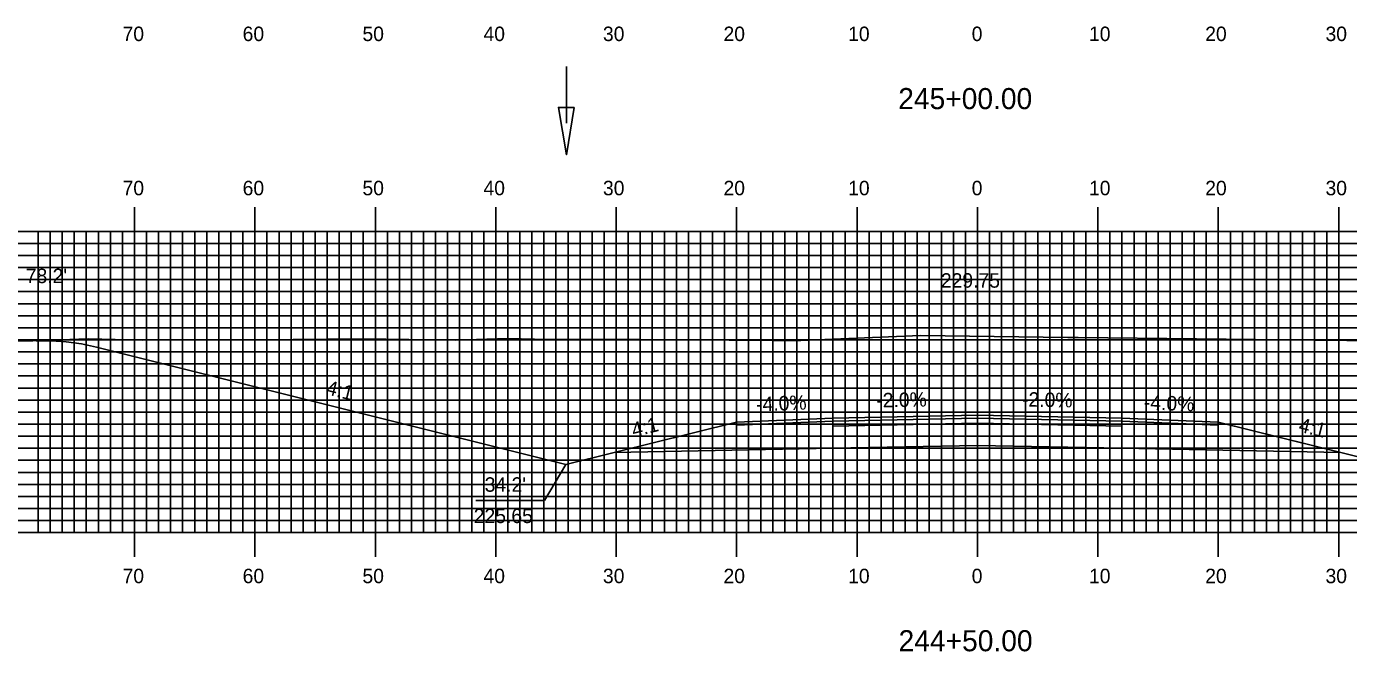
# Model space of a CAD drawing. Extents: x 1802716 to 1803060, y 442591 to 442811.
# Drawn here: x 1802803.1 to 1802912.9, y 442698.8 to 442750.7 of the extents above; entities that cross this region are included whole.
import ezdxf

# ---------------------------------------------------------------- set-up
doc = ezdxf.new("R2010")
doc.units = 0
for name, color, linetype in [('ANNOTATION', 7, 'Continuous'), ('D_Drainage_Ditch_Line', 7, 'Continuous'), ('D_Roadway_Centerline', 7, 'Continuous'), ('D_Roadway_Centerline_Text', 7, 'Continuous'), ('D_Roadway_Edge_Shoulder', 7, 'Continuous'), ('D_Roadway_Edge_TW', 7, 'Continuous'), ('D_Roadway_Pavement', 7, 'Continuous'), ('D_Roadway_SlopeLines', 7, 'Continuous'), ('D_Roadway_SubGrade', 7, 'Continuous'), ('D_Text_Standard', 7, 'Continuous'), ('H_V ANNOTATION', 7, 'Continuous'), ('MAJOR', 7, 'Continuous'), ('MINOR', 7, 'Continuous'), ('S_Roadway_Centerline', 7, 'Continuous')]:
    doc.layers.add(name, color=color, linetype=linetype)

msp = doc.modelspace()

# ---------------------------------------------------------------- linework, layer by layer
at = {"layer": 'ANNOTATION'}
msp.add_lwpolyline([(1802840.46, 442711.33), (1802846.15, 442711.33), (1802847.94, 442714.31)], dxfattribs=at)
at = {"layer": 'D_Drainage_Ditch_Line'}
msp.add_line((1802847.97, 442742.65), (1802847.97, 442747.35), dxfattribs=at)
msp.add_lwpolyline([(1802848.62, 442743.96), (1802847.31, 442743.96), (1802847.97, 442740.03)], close=True, dxfattribs=at)
at = {"layer": 'D_Roadway_Centerline'}
msp.add_lwpolyline([(1802803.95, 442724.6), (1802805.2, 442724.6), (1802806.45, 442724.51), (1802807.7, 442724.33), (1802808.95, 442724.06), (1802847.94, 442714.31), (1802851.94, 442715.31), (1802862.11, 442717.85), (1802870.11, 442718.17), (1802882.11, 442718.41), (1802894.11, 442718.17), (1802902.11, 442717.85), (1802912.29, 442715.31), (1802916.29, 442714.31), (1802956.49, 442724.36), (1802957.74, 442724.64), (1802958.99, 442724.84), (1802960.24, 442724.97), (1802961.49, 442725.02)], dxfattribs=at)
at = {"layer": 'D_Roadway_Edge_Shoulder'}
for points in [[(1802870.11, 442718.17), (1802862.11, 442717.85), (1802862.11, 442717.6), (1802870.11, 442717.92)], [(1802894.11, 442718.17), (1802902.11, 442717.85), (1802902.11, 442717.6), (1802894.11, 442717.92)]]:
    msp.add_lwpolyline(points, close=True, dxfattribs=at)
at = {"layer": 'D_Roadway_Edge_TW'}
msp.add_lwpolyline([(1802870.11, 442717.92), (1802870.11, 442718.17), (1802882.11, 442718.41), (1802894.11, 442718.17), (1802894.11, 442717.92), (1802882.11, 442718.16)], close=True, dxfattribs=at)
at = {"layer": 'D_Roadway_Pavement'}
msp.add_lwpolyline([(1802870.11, 442717.51), (1802870.11, 442717.92), (1802882.11, 442718.16), (1802894.11, 442717.92), (1802894.11, 442717.51), (1802882.11, 442717.75)], close=True, dxfattribs=at)
at = {"layer": 'D_Roadway_SlopeLines'}
for points in [[(1802847.94, 442714.31), (1802808.95, 442724.06), (1802807.7, 442724.33), (1802806.45, 442724.51), (1802805.2, 442724.6), (1802803.95, 442724.6)], [(1802862.11, 442717.85), (1802847.94, 442714.31)], [(1802902.11, 442717.85), (1802916.29, 442714.31)]]:
    msp.add_lwpolyline(points, dxfattribs=at)
at = {"layer": 'D_Roadway_SubGrade'}
msp.add_lwpolyline([(1802870.11, 442715.67), (1802851.94, 442715.31), (1802862.11, 442717.85), (1802862.11, 442717.6), (1802870.11, 442717.92), (1802882.11, 442718.16), (1802894.11, 442717.92), (1802902.11, 442717.6), (1802902.11, 442717.85), (1802912.29, 442715.31), (1802894.11, 442715.67), (1802882.11, 442715.91)], close=True, dxfattribs=at)
at = {"layer": 'MAJOR'}
for p, q in [((1802812.11, 442735.67), (1802812.11, 442733.67)), ((1802822.11, 442735.67), (1802822.11, 442733.67)), ((1802832.11, 442735.67), (1802832.11, 442733.67)), ((1802842.11, 442735.67), (1802842.11, 442733.67)), ((1802852.11, 442735.67), (1802852.11, 442733.67)), ((1802862.11, 442735.67), (1802862.11, 442733.67)), ((1802872.11, 442735.67), (1802872.11, 442733.67)), ((1802882.11, 442735.67), (1802882.11, 442733.67)), ((1802892.11, 442735.67), (1802892.11, 442733.67)), ((1802902.11, 442735.67), (1802902.11, 442733.67)), ((1802912.11, 442735.67), (1802912.11, 442733.67)), ((1802742.11, 442733.67), (1803022.11, 442733.67)), ((1802742.11, 442733.67), (1803022.11, 442733.67)), ((1802812.11, 442708.67), (1802812.11, 442733.67)), ((1802822.11, 442708.67), (1802822.11, 442733.67)), ((1802832.11, 442708.67), (1802832.11, 442733.67)), ((1802842.11, 442708.67), (1802842.11, 442733.67)), ((1802852.11, 442708.67), (1802852.11, 442733.67)), ((1802862.11, 442708.67), (1802862.11, 442733.67)), ((1802872.11, 442708.67), (1802872.11, 442733.67)), ((1802882.11, 442708.67), (1802882.11, 442733.67)), ((1802892.11, 442708.67), (1802892.11, 442733.67)), ((1802902.11, 442708.67), (1802902.11, 442733.67)), ((1802912.11, 442708.67), (1802912.11, 442733.67)), ((1802742.11, 442728.67), (1803022.11, 442728.67)), ((1802742.11, 442723.67), (1803022.11, 442723.67)), ((1802742.11, 442718.67), (1803022.11, 442718.67)), ((1802742.11, 442713.67), (1803022.11, 442713.67)), ((1802742.11, 442708.67), (1803022.11, 442708.67)), ((1802742.11, 442708.67), (1803022.11, 442708.67)), ((1802812.11, 442706.66), (1802812.11, 442708.67)), ((1802822.11, 442706.66), (1802822.11, 442708.67)), ((1802832.11, 442706.66), (1802832.11, 442708.67)), ((1802842.11, 442706.66), (1802842.11, 442708.67)), ((1802852.11, 442706.66), (1802852.11, 442708.67)), ((1802862.11, 442706.66), (1802862.11, 442708.67)), ((1802872.11, 442706.66), (1802872.11, 442708.67)), ((1802882.11, 442706.66), (1802882.11, 442708.67)), ((1802892.11, 442706.66), (1802892.11, 442708.67)), ((1802902.11, 442706.66), (1802902.11, 442708.67)), ((1802912.11, 442706.66), (1802912.11, 442708.67))]:
    msp.add_line(p, q, dxfattribs=at)
at = {"layer": 'MINOR'}
for p, q in [((1802804.11, 442708.67), (1802804.11, 442733.67)), ((1802805.11, 442708.67), (1802805.11, 442733.67)), ((1802806.11, 442708.67), (1802806.11, 442733.67)), ((1802807.11, 442708.67), (1802807.11, 442733.67)), ((1802808.11, 442708.67), (1802808.11, 442733.67)), ((1802809.11, 442708.67), (1802809.11, 442733.67)), ((1802810.11, 442708.67), (1802810.11, 442733.67)), ((1802811.11, 442708.67), (1802811.11, 442733.67)), ((1802813.11, 442708.67), (1802813.11, 442733.67)), ((1802814.11, 442708.67), (1802814.11, 442733.67)), ((1802815.11, 442708.67), (1802815.11, 442733.67)), ((1802816.11, 442708.67), (1802816.11, 442733.67)), ((1802817.11, 442708.67), (1802817.11, 442733.67)), ((1802818.11, 442708.67), (1802818.11, 442733.67)), ((1802819.11, 442708.67), (1802819.11, 442733.67)), ((1802820.11, 442708.67), (1802820.11, 442733.67)), ((1802821.11, 442708.67), (1802821.11, 442733.67)), ((1802823.11, 442708.67), (1802823.11, 442733.67)), ((1802824.11, 442708.67), (1802824.11, 442733.67)), ((1802825.11, 442708.67), (1802825.11, 442733.67)), ((1802826.11, 442708.67), (1802826.11, 442733.67)), ((1802827.11, 442708.67), (1802827.11, 442733.67)), ((1802828.11, 442708.67), (1802828.11, 442733.67)), ((1802829.11, 442708.67), (1802829.11, 442733.67)), ((1802830.11, 442708.67), (1802830.11, 442733.67)), ((1802831.11, 442708.67), (1802831.11, 442733.67)), ((1802833.11, 442708.67), (1802833.11, 442733.67)), ((1802834.11, 442708.67), (1802834.11, 442733.67)), ((1802835.11, 442708.67), (1802835.11, 442733.67)), ((1802836.11, 442708.67), (1802836.11, 442733.67)), ((1802837.11, 442708.67), (1802837.11, 442733.67)), ((1802838.11, 442708.67), (1802838.11, 442733.67)), ((1802839.11, 442708.67), (1802839.11, 442733.67)), ((1802840.11, 442708.67), (1802840.11, 442733.67)), ((1802841.11, 442708.67), (1802841.11, 442733.67)), ((1802843.11, 442708.67), (1802843.11, 442733.67)), ((1802844.11, 442708.67), (1802844.11, 442733.67)), ((1802845.11, 442708.67), (1802845.11, 442733.67)), ((1802846.11, 442708.67), (1802846.11, 442733.67)), ((1802847.11, 442708.67), (1802847.11, 442733.67)), ((1802848.11, 442708.67), (1802848.11, 442733.67)), ((1802849.11, 442708.67), (1802849.11, 442733.67)), ((1802850.11, 442708.67), (1802850.11, 442733.67)), ((1802851.11, 442708.67), (1802851.11, 442733.67)), ((1802853.11, 442708.67), (1802853.11, 442733.67)), ((1802854.11, 442708.67), (1802854.11, 442733.67)), ((1802855.11, 442708.67), (1802855.11, 442733.67)), ((1802856.11, 442708.67), (1802856.11, 442733.67)), ((1802857.11, 442708.67), (1802857.11, 442733.67)), ((1802858.11, 442708.67), (1802858.11, 442733.67)), ((1802859.11, 442708.67), (1802859.11, 442733.67)), ((1802860.11, 442708.67), (1802860.11, 442733.67)), ((1802861.11, 442708.67), (1802861.11, 442733.67)), ((1802863.11, 442708.67), (1802863.11, 442733.67)), ((1802864.11, 442708.67), (1802864.11, 442733.67)), ((1802865.11, 442708.67), (1802865.11, 442733.67)), ((1802866.11, 442708.67), (1802866.11, 442733.67)), ((1802867.11, 442708.67), (1802867.11, 442733.67)), ((1802868.11, 442708.67), (1802868.11, 442733.67)), ((1802869.11, 442708.67), (1802869.11, 442733.67)), ((1802870.11, 442708.67), (1802870.11, 442733.67)), ((1802871.11, 442708.67), (1802871.11, 442733.67)), ((1802873.11, 442708.67), (1802873.11, 442733.67)), ((1802874.11, 442708.67), (1802874.11, 442733.67)), ((1802875.11, 442708.67), (1802875.11, 442733.67)), ((1802876.11, 442708.67), (1802876.11, 442733.67)), ((1802877.11, 442708.67), (1802877.11, 442733.67)), ((1802878.11, 442708.67), (1802878.11, 442733.67)), ((1802879.11, 442708.67), (1802879.11, 442733.67)), ((1802880.11, 442708.67), (1802880.11, 442733.67)), ((1802881.11, 442708.67), (1802881.11, 442733.67)), ((1802883.11, 442708.67), (1802883.11, 442733.67)), ((1802884.11, 442708.67), (1802884.11, 442733.67)), ((1802885.11, 442708.67), (1802885.11, 442733.67)), ((1802886.11, 442708.67), (1802886.11, 442733.67)), ((1802887.11, 442708.67), (1802887.11, 442733.67)), ((1802888.11, 442708.67), (1802888.11, 442733.67)), ((1802889.11, 442708.67), (1802889.11, 442733.67)), ((1802890.11, 442708.67), (1802890.11, 442733.67)), ((1802891.11, 442708.67), (1802891.11, 442733.67)), ((1802893.11, 442708.67), (1802893.11, 442733.67)), ((1802894.11, 442708.67), (1802894.11, 442733.67)), ((1802895.11, 442708.67), (1802895.11, 442733.67)), ((1802896.11, 442708.67), (1802896.11, 442733.67)), ((1802897.11, 442708.67), (1802897.11, 442733.67)), ((1802898.11, 442708.67), (1802898.11, 442733.67)), ((1802899.11, 442708.67), (1802899.11, 442733.67)), ((1802900.11, 442708.67), (1802900.11, 442733.67)), ((1802901.11, 442708.67), (1802901.11, 442733.67)), ((1802903.11, 442708.67), (1802903.11, 442733.67)), ((1802904.11, 442708.67), (1802904.11, 442733.67)), ((1802905.11, 442708.67), (1802905.11, 442733.67)), ((1802906.11, 442708.67), (1802906.11, 442733.67)), ((1802907.11, 442708.67), (1802907.11, 442733.67)), ((1802908.11, 442708.67), (1802908.11, 442733.67)), ((1802909.11, 442708.67), (1802909.11, 442733.67)), ((1802910.11, 442708.67), (1802910.11, 442733.67)), ((1802911.11, 442708.67), (1802911.11, 442733.67)), ((1802742.11, 442732.67), (1803022.11, 442732.67)), ((1802742.11, 442731.67), (1803022.11, 442731.67)), ((1802742.11, 442730.67), (1803022.11, 442730.67)), ((1802742.11, 442729.67), (1803022.11, 442729.67)), ((1802742.11, 442727.67), (1803022.11, 442727.67)), ((1802742.11, 442726.67), (1803022.11, 442726.67)), ((1802742.11, 442725.67), (1803022.11, 442725.67)), ((1802742.11, 442724.67), (1803022.11, 442724.67)), ((1802742.11, 442722.67), (1803022.11, 442722.67)), ((1802742.11, 442721.67), (1803022.11, 442721.67)), ((1802742.11, 442720.67), (1803022.11, 442720.67)), ((1802742.11, 442719.67), (1803022.11, 442719.67)), ((1802742.11, 442717.67), (1803022.11, 442717.67)), ((1802742.11, 442716.67), (1803022.11, 442716.67)), ((1802742.11, 442715.67), (1803022.11, 442715.67)), ((1802742.11, 442714.67), (1803022.11, 442714.67)), ((1802742.11, 442712.67), (1803022.11, 442712.67)), ((1802742.11, 442711.67), (1803022.11, 442711.67)), ((1802742.11, 442710.67), (1803022.11, 442710.67)), ((1802742.11, 442709.67), (1803022.11, 442709.67))]:
    msp.add_line(p, q, dxfattribs=at)
at = {"layer": 'S_Roadway_Centerline'}
msp.add_lwpolyline([(1802787.46, 442724.56), (1802803.66, 442724.59), (1802808.26, 442724.74), (1802812.78, 442724.64), (1802825.29, 442724.71), (1802831.04, 442724.74), (1802838.77, 442724.64), (1802843.1, 442724.77), (1802846.44, 442724.7), (1802854.11, 442724.7), (1802865.21, 442724.62), (1802866.49, 442724.61), (1802867.43, 442724.61), (1802877.39, 442725.02), (1802889.61, 442724.87), (1802890.03, 442724.86), (1802890.47, 442724.86), (1802910.13, 442724.65), (1802912.77, 442724.61), (1802916.02, 442724.62)], dxfattribs=at)

# ---------------------------------------------------------------- texts
at = {"layer": 'ANNOTATION'}
for s, rotation, p in [('4:1', 345.9638, (1802827.95, 442720.17)), ('-4.0%', 2.2906, (1802863.75, 442718.72)), ('-2.0%', 1.1458, (1802873.72, 442719.05)), ('-2.0%', 358.8542, (1802885.8, 442719.14)), ('-4.0%', 357.7094, (1802895.91, 442718.9)), ('4:1', 14.0362, (1802853.56, 442716.58)), ('4:1', 345.9638, (1802908.71, 442717.07))]:
    msp.add_text(s, height=1.2, rotation=rotation, dxfattribs=at).set_placement(p)
for s, p in [("34.2'", (1802841.19, 442712.06)), ('225.65', (1802840.28, 442709.46))]:
    msp.add_text(s, height=1.2, dxfattribs=at).set_placement(p)
at = {"layer": 'D_Roadway_Centerline'}
for s in ['C', 'L']:
    msp.add_text(s, height=0.0146, dxfattribs=at).set_placement((1802882.11, 442718.41))
at = {"layer": 'D_Roadway_Centerline_Text'}
msp.add_text('229.75', height=1.2, dxfattribs=at).set_placement((1802879.07, 442729))
at = {"layer": 'D_Text_Standard'}
msp.add_text("78.2'", height=1.2, dxfattribs=at).set_placement((1802803.08, 442729.38))
at = {"layer": 'H_V ANNOTATION'}
for s, height, p in [('70', 1.2, (1802811.12, 442749.47)), ('60', 1.2, (1802821.09, 442749.47)), ('50', 1.2, (1802831.04, 442749.47)), ('40', 1.2, (1802841.09, 442749.47)), ('30', 1.2, (1802851.01, 442749.47)), ('20', 1.2, (1802861.02, 442749.47)), ('10', 1.2, (1802871.37, 442749.47)), ('0', 1.2, (1802881.63, 442749.47)), ('10', 1.2, (1802891.37, 442749.47)), ('20', 1.2, (1802901.02, 442749.47)), ('30', 1.2, (1802911.01, 442749.47)), ('245+00.00', 1.75, (1802875.53, 442743.82)), ('70', 1.2, (1802811.12, 442736.67)), ('60', 1.2, (1802821.09, 442736.67)), ('50', 1.2, (1802831.04, 442736.67)), ('40', 1.2, (1802841.09, 442736.67)), ('30', 1.2, (1802851.01, 442736.67)), ('20', 1.2, (1802861.02, 442736.67)), ('10', 1.2, (1802871.37, 442736.67)), ('0', 1.2, (1802881.63, 442736.67)), ('10', 1.2, (1802891.37, 442736.67)), ('20', 1.2, (1802901.02, 442736.67)), ('30', 1.2, (1802911.01, 442736.67)), ('70', 1.2, (1802811.12, 442704.47)), ('60', 1.2, (1802821.09, 442704.47)), ('50', 1.2, (1802831.04, 442704.47)), ('40', 1.2, (1802841.09, 442704.47)), ('30', 1.2, (1802851.01, 442704.47)), ('20', 1.2, (1802861.02, 442704.47)), ('10', 1.2, (1802871.37, 442704.47)), ('0', 1.2, (1802881.63, 442704.47)), ('10', 1.2, (1802891.37, 442704.47)), ('20', 1.2, (1802901.02, 442704.47)), ('30', 1.2, (1802911.01, 442704.47)), ('244+50.00', 1.75, (1802875.56, 442698.82))]:
    msp.add_text(s, height=height, dxfattribs=at).set_placement(p)

doc.saveas('drawing.dxf')
